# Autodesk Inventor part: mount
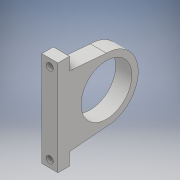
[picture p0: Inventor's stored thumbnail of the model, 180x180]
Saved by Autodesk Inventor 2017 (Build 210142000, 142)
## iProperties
Created: 2017-04
Part Number: mount
Material: Generic
Document SubType Name: Modeling
Designer: s4321966
Density: 1 g/cm^3
Appearance: Default
Author: s4321966
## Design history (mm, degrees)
sketch "Sketch1" dims "d6" = 27.5
  geometry: L1 (0, 0)-(0, -21); L2 (0, 0)-(21, 0); L3 (0, 0)-(-21, 0); L4 (0, 0)-(21, 0); L5 (0, -13.75)-(28.06, -13.75); L6 (-21, 0)-(-21, -15.587); L7 (-21, -15.587)-(0, -13.75); L8 (-21, 0)-(-21, 15.587); L9 (-21, 15.587)-(0, 13.75); L10 (-21, 15.587)-(-21, 20.587); L11 (-21, 15.587)-(-16, 15.587); L12 (-21, 20.587)-(-16, 20.587); L13 (-16, 20.587)-(-21, 20.587); L14 (-21, 20.587)-(-21, 0); L15 (-21, 0)-(-16, 0); L16 (-16, 0)-(-16, 20.587); L17 (-21, 0)-(-21, -15.587); L18 (-21, -15.587)-(-16, -15.587); L19 (-21, -20.587)-(-21, 0); L20 (-21, -15.587)-(-21, -20.587); L21 (-21, -20.587)-(-16, -20.587); L22 (-16, -20.587)-(-21, -20.587); L23 (-16, 0)-(-16, -20.587); L24 (0, 13.75)-(-8.153, 9.41); L25 (-8.153, 9.41)-(-12.797, 1.511); L26 (-12.797, 1.511)-(-11.3, -5.53); L27 (-11.3, -5.53)-(-6.721, -9.817); L28 (-6.721, -9.817)-(0, -13.75); L29 (-16, 15.15)-(-16, -15.15); C1 r 11 at (0, 0); 2 further points
  constraints: 58 end point, 6 horizontal, 6 symmetric about line, 5 point on line, 3 equal length, 3 vertical, 2 parallel, 2 perpendicular, 1 centre point, 1 coincident, 1 vertical alignment, 2 other
  dimensions: "d0" = 22 diameter of C1; "d1" = 21 distance of L1.start L1.end; "d2" = 90 deg angle of L1 L2 (derived); "d3" = 21 distance of L1.start L3.end; "d4" = 180 deg angle of L3 L4 (derived); "d8" = 5 distance of L8.end L10.end; "d9" = 90 deg angle of L11 L10 (derived); "d10" = 5 distance of L10.end L12.end; "d11" = 90 deg angle of L10 L12 (derived)
extrude "Extrusion1" new body sketch "Sketch1" distance "d12" = 7; taper "d13" = 0 deg
sketch "Sketch2"
  geometry: L1 (0, -35.737)-(0, 5.437) reference; L2 (0, -15.15)-(0, 5.437); L3 (0, -15.15)-(23.913, -15.15); L4 (7, -35.737)-(7, 5.437) reference; L5 (7, -0.204)-(0, 4.743); L6 (7, -30.095)-(0, -35.043); C1 r 1.5 at (3.5, 2.269); C2 r 1.5 at (3.5, -32.569)
  constraints: 8 end point, 3 symmetric about line, 2 centre point, 2 point on line, 1 collinear, 1 horizontal, 1 other
  dimensions: "d14" = 3 diameter of C1
extrude "Extrusion2" cut sketch "Sketch2" distance "d15" = 7; taper "d16" = 0 deg
body "Solid1"
